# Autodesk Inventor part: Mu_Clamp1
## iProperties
Shininess: 64.0
Length Units: 11272
Angle Units: 11279
Time Units: 11290
Mass Units: 11286
Length Display Precision: 3
Angle Display Precision: 2
Compacted: True
Part Number: Mu_Clamp1
Document SubType Name: Modeling
Created: 2004-08
Designer: John Blackburn
Manufacturer: Standard
Standards Organization: Custom
Material: Aluminum-6061
Density: 0.0
Volumn: 0.0
Area: 0.0
PropertySet Name: Model Information
Control State: 0
Master: False
Checked Out: False
Author: John Blackburn
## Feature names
1. Extrusion1
2. Extrusion2
3. Hole1
